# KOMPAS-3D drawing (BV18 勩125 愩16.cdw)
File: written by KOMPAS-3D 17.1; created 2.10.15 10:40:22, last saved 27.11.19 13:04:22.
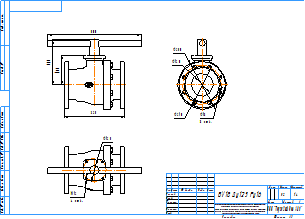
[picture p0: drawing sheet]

Sheet 1: A3, landscape

Title block, sheet 1: name: BV18 Ду125 Ру16; material: Сталь 10  ГОСТ 1050-88; mass: 52; sheets: 1; sheet format: A3; stored path: C:\Users\kka\KOMPAS_Work\!Trash\BV18\KOMPAS 2D\BV18 Ду100 Ру16 с голым штоком.cdw

Views: Спереди 4, Проекционный вид 5
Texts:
  Klimkovich
  ADL
  Рама для чертежей
  Лит-Масса-Масштаб
  Материал-Предприятие
  Масштаб
  Изм.
  Лист
  № докум.
  Подп.
  Дата
  Лит.
  Разраб.
  Пров.
  Т.контр.
  Листов
  Внимание! Данный продукт является объектом авторского права ООО «Торговый Дом АДЛ».
  Запрещается изменение, копирование, распространение
  (в том числе путем копирования на другие сайты и ресурсы в Интернете)
  или любое иное использование информации и объектов без предварительного
  согласия правообладателя (ООО «Торговый Дом АДЛ»).
  Н.контр.
  Утв.
  ООО "Торговый дом АДЛ"
  Изменение
  Номер документа
  Подпись
  Обозначение документа
  Наименование изделия
  Масса изделия по ГОСТ 2.109-73
  Порядковый номер листа
  Общее количество листов в документе
  Характер работы, выполненной лицом, подписавшим документ
  Наименование или индекс предприятия, выпускающего документ
  Инв. № подл.
  Подп. и дата
  Взам. инв. №
  Инв. № дубл.
  Инвентарный номер подлинника по ГОСТ 2.501-68
  Подпись принявшего подлинник в отдел технической документации
  Инвентарный номер подлинника, взамен которого выпущен данный подлинник
  Инвентарный номер дубликата по ГОСТ 2.502-68
  Подпись принявшего дубликат в отдел технической документации
  Справ. №
  Перв. примен.
  Обозначение документа, взамен или на основании которого выпущен данный документ
  Обозначение документа, в котором впервые записан данный документ
  Подпись лица, копировавшего чертеж
  Обозначение формата листа
  !Рама для чертежа
Dimensions and other numbers on the sheet: 325; 160; 500; 242; 125; 12; 4 отв.; 1:4; 1; 52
